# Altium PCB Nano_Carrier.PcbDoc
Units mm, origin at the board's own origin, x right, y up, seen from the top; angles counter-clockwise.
Board outline 50 x 80 mm, 4 copper layers (Top, PWR, MID, Bottom), stack 1.612 mm thick; 1 components, 29 nets, 34 pads, 0 vias.
Unrouted connection lines stored in the file: 1.
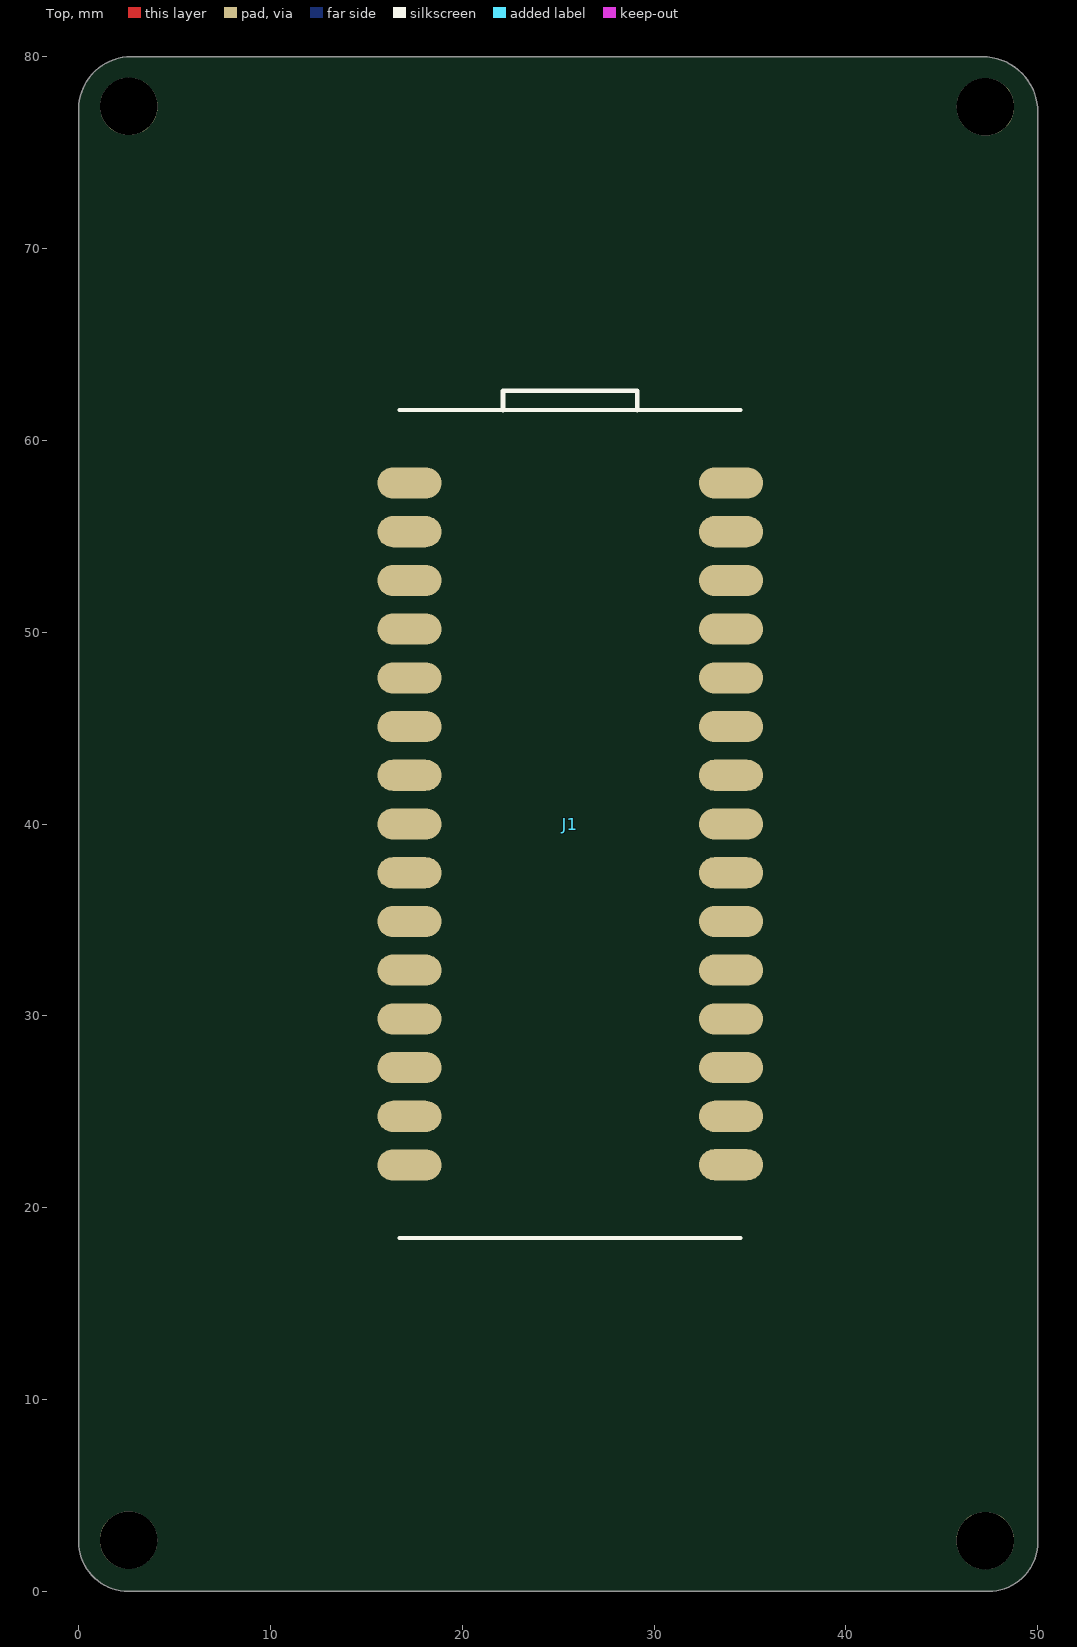
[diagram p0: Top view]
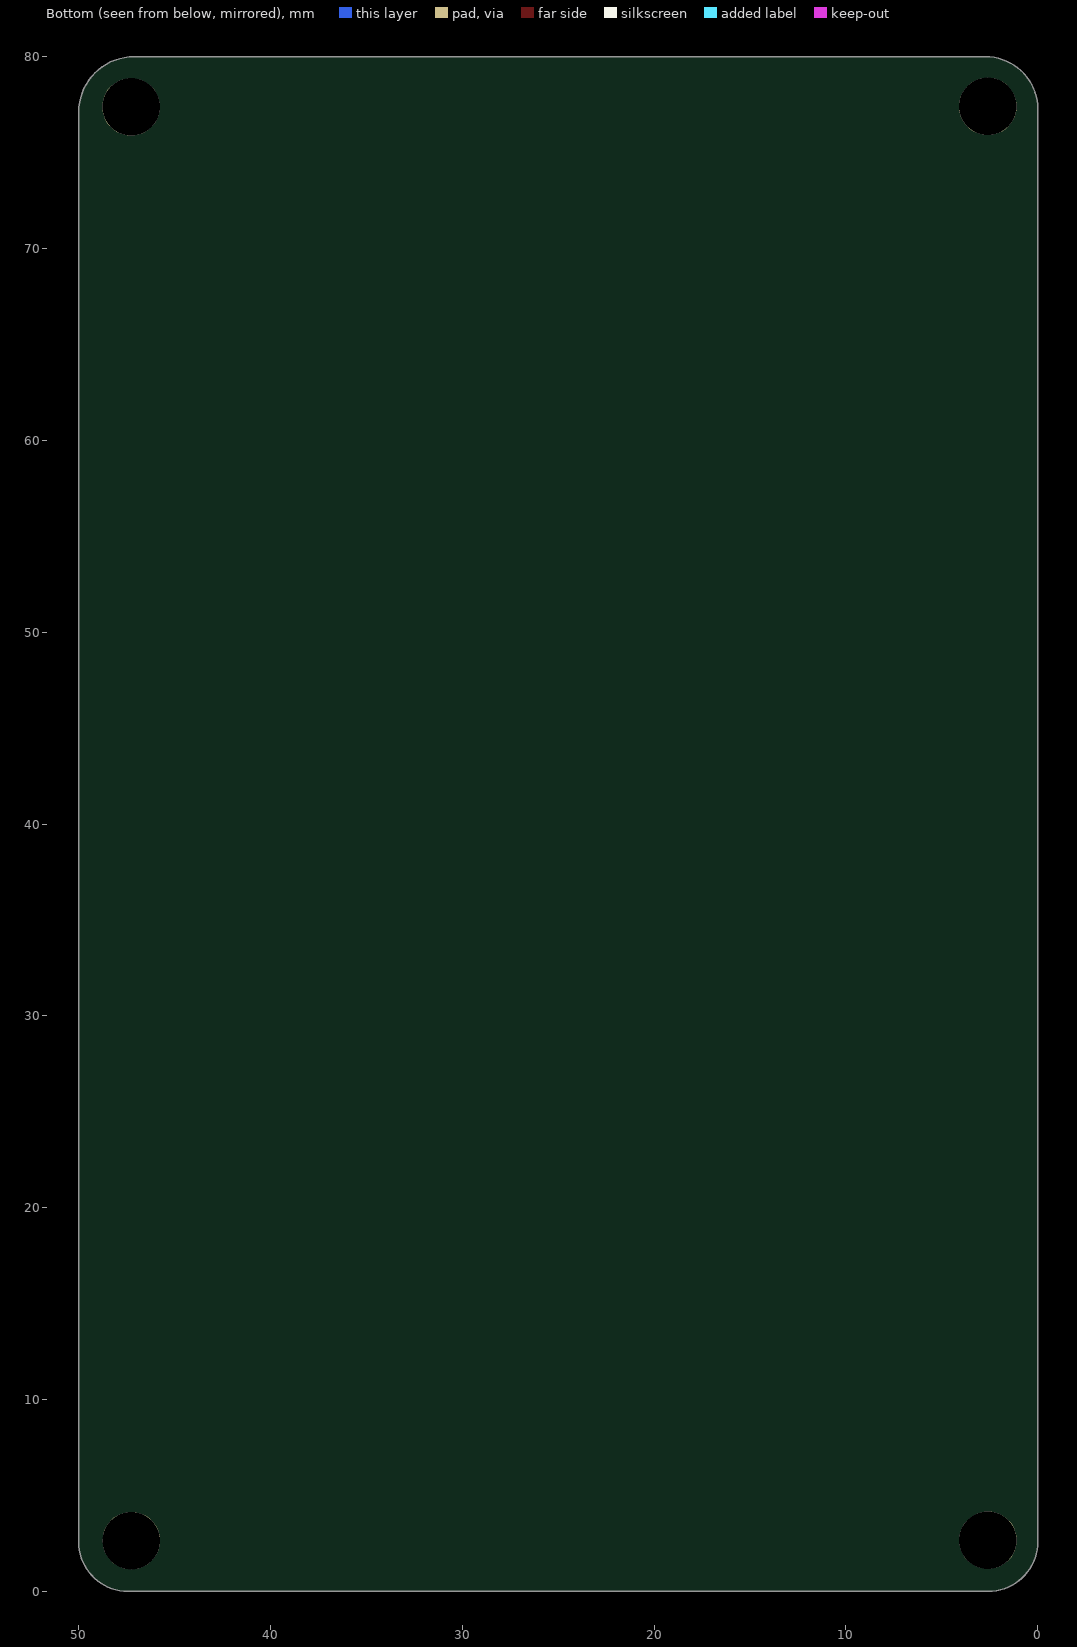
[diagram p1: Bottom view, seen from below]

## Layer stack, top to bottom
Top Solder: solder mask 0.01, Solder Resist, Dk 3.5
Top: signal copper 0.035
Dielectric 1: core 0.356, FR-4, Dk 4.8
PWR: signal copper 0.035
Dielectric3: core 0.76, FR-4, Dk 4.8
MID: signal copper 0.035
Dielectric2: dielectric 0.356, FR-4, Dk 4.8
Bottom: signal copper 0.035
Bottom Solder: solder mask 0.0102, Solder Resist, Dk 3.5

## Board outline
47.437,0 2.583,0 cw(c2.583,2.583) 0,2.583 0,77.275 cw(c2.725,77.275) 2.725,80 47.122,80 cw(c47.122,77.122) 50,77.122 50,2.574 cw(c47.437,2.563)

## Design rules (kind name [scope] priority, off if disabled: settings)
Clearance "Clearance (Same Net)" [All] p1: gap=0.178 ignorepadtopadclearanceinfootprint=FALSE except(0.152: SMDPad-SMDPad SMDPad-THPad SMDPad-Via)
Clearance [All] p2: gap=0.178 ignorepadtopadclearanceinfootprint=FALSE
HoleSize [All] p1: absolutevalues=TRUE maxlimit=2540 minlimit=0.3 maxpercent=80.000 minpercent=20.000
HoleToHoleClearance mdDrill [All] p1: gap=0.254 allowstackedmicrovias=TRUE
PasteMaskExpansion Expansion_SMDPaste_OFF [InPadClass('SMDPaste_OFF')] p1: expansion=0
PasteMaskExpansion mlMinCreamFrame [All] p2: expansion=0
PolygonConnect PolygonConnect_For_PolygonThermal_ON_Width120000_Gap100000 [InPolygonClass('PolygonThermal_ON_Width120000_Gap100000')] p1: connectstyle=Relief reliefconductorwidth=0.305 reliefentries=4 polygonreliefangle="90 Angle" airgapwidth=0.254
PolygonConnect PolygonConnect_For_PolygonThermal_OFF [InPolygonClass('PolygonThermal_OFF')] p2: connectstyle=Direct reliefconductorwidth=0.254 reliefentries=4 polygonreliefangle="90 Angle" airgapwidth=0.254
PolygonConnect PolygonConnect_For_PolygonThermal_ON_Width160000_Gap100000 [InPolygonClass('PolygonThermal_ON_Width160000_Gap100000')] p3: connectstyle=Relief reliefconductorwidth=0.406 reliefentries=4 polygonreliefangle="90 Angle" airgapwidth=0.254
PolygonConnect ThermalVias [IsVia] p4: connectstyle=Direct reliefconductorwidth=0.254 reliefentries=4 polygonreliefangle="90 Angle" airgapwidth=0.254
PolygonConnect [All] p5: connectstyle=Relief reliefconductorwidth=0.254 reliefentries=4 polygonreliefangle="90 Angle" airgapwidth=0.254
RoomDefinition NANO-1 [InComponentClass('NANO-1')] p1: confinementstyle=ConfineIn formatcopy=TRUE lockcomponents=FALSE outline 12.1,12.1 37.8,12.1 37.8,80.4 12.1,80.4
RoutingVias [All] p1: holewidth=0.3 width=0.706 viastyle="Through Hole" minholewidth=0.3 minwidth=0.706 maxholewidth=2.54 maxwidth=2.54
SolderMaskExpansion Expansion_SMDSolder_OFF [InPadClass('SMDSolder_OFF')] p1: expansion=0 istentingtop=FALSE
SolderMaskExpansion mlMinStopFrame [All] p2: expansion=0.1 istentingtop=FALSE
Width [All] p1: maxlimit=254 minlimit=0.3 preferedwidth=0.3
27 further rules are at their usual default settings.

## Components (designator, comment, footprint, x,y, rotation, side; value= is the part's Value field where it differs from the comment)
J1 "NanoCarrier-Footprint (Hand Soldering)" "NanoCarrier-Footprint (Hand Soldering)-Footprint-1" 16.728,61.59 r270 top

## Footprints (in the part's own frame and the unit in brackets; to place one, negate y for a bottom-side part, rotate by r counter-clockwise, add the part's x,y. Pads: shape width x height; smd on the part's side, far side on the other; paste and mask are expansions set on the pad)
"NanoCarrier-Footprint (Hand Soldering)-Footprint-1" [mil] "Default PCB Component"
  oval 63.94x131.81 smd: 1(150,20) 2(250,20) 3(350,20) 4(450,20) 5(550,20) 6(650,20) 7(750,20) 8(850,20) 9(950,20) 10(1050,20) 11(1150,20) 12(1250,20) 13(1350,20) 14(1450,20) 15(1550,20) 16(1549.41,680) 17(1450,680) 18(1350,680) 19(1250,680) 20(1150,680) 21(1050,680) 22(950,680) 23(850,680) 24(750,680) 25(650,680) 26(550,680) 27(450,680) 28(350,680) 29(250,680) 30(150,680)
  silkscreen extent -39,0 1700,700

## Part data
J1: library part AF0004-A.2

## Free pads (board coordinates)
  round 3 hole 3 unplated: MH1(2.6,2.66) MH2(47.26,2.64) MH3(47.27,77.39) MH4(2.61,77.41)

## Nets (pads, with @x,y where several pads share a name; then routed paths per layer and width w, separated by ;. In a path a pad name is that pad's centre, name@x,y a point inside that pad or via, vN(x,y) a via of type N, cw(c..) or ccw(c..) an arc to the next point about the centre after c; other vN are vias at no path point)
+3.3V: J1.2
+VM2: J1.15
A0: J1.4
A1: J1.5
A2: J1.6
A3: J1.7
A4: J1.8
A5: J1.9
A6: J1.10
A7: J1.11
AREF: J1.3
D2: J1.20
D3: J1.21
D4: J1.22
D5: J1.23
D6: J1.24
D7: J1.25
D8: J1.26
D9: J1.27
D10: J1.28
GND: J1.14 J1.19
MISO: J1.30
MOSI: J1.29
RST_NANO1: J1.18
RST_NANO2: J1.13
RX: J1.17
SCK: J1.1
TX: J1.16
VBUS: J1.12

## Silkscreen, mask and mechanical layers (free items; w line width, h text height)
Board (Mech4):
  the board outline again, w0.127

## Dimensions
32.62,58.32 to 50,77.122 on Dimensions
